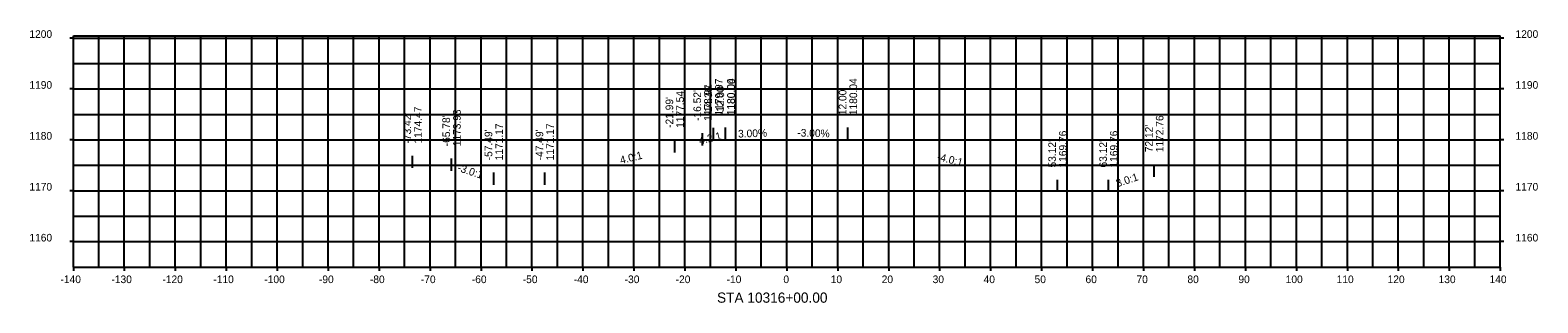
# Model space of a CAD drawing. Extents: x -148 to 147, y 1148 to 1202.
import ezdxf

# ---------------------------------------------------------------- set-up
doc = ezdxf.new("R2010")
doc.units = 0
for name, color, linetype in [('SheetBorder', 7, 'Continuous'), ('SheetGridMajor', 7, 'Continuous'), ('SheetGridMinor', 7, 'Continuous'), ('SheetText', 7, 'Continuous'), ('Text', 7, 'Continuous')]:
    doc.layers.add(name, color=color, linetype=linetype)

msp = doc.modelspace()

# ---------------------------------------------------------------- linework, layer by layer
at = {"layer": 'SheetBorder'}
for p, q in [((-140, 1200.4), (140, 1200.4)), ((-140, 1155), (-140, 1200.4)), ((140, 1155), (140, 1200.4)), ((-140, 1155), (140, 1155))]:
    msp.add_line(p, q, dxfattribs=at)
at = {"layer": 'SheetGridMajor'}
for p, q in [((-140, 1200), (-140.72, 1200)), ((-140, 1200), (140, 1200)), ((-130, 1155), (-130, 1200.4)), ((-120, 1155), (-120, 1200.4)), ((-110, 1155), (-110, 1200.4)), ((-100, 1155), (-100, 1200.4)), ((-90, 1155), (-90, 1200.4)), ((-80, 1155), (-80, 1200.4)), ((-70, 1155), (-70, 1200.4)), ((-60, 1155), (-60, 1200.4)), ((-50, 1155), (-50, 1200.4)), ((-40, 1155), (-40, 1200.4)), ((-30, 1155), (-30, 1200.4)), ((-20, 1155), (-20, 1200.4)), ((-10, 1155), (-10, 1200.4)), ((0, 1155), (0, 1200.4)), ((10, 1155), (10, 1200.4)), ((20, 1155), (20, 1200.4)), ((30, 1155), (30, 1200.4)), ((40, 1155), (40, 1200.4)), ((50, 1155), (50, 1200.4)), ((60, 1155), (60, 1200.4)), ((70, 1155), (70, 1200.4)), ((80, 1155), (80, 1200.4)), ((90, 1155), (90, 1200.4)), ((100, 1155), (100, 1200.4)), ((110, 1155), (110, 1200.4)), ((120, 1155), (120, 1200.4)), ((130, 1155), (130, 1200.4)), ((140.72, 1200), (140, 1200)), ((-140, 1190), (-140.72, 1190)), ((-140, 1190), (140, 1190)), ((140.72, 1190), (140, 1190)), ((-140, 1180), (-140.72, 1180)), ((-140, 1180), (140, 1180)), ((140.72, 1180), (140, 1180)), ((-140, 1170), (-140.72, 1170)), ((-140, 1170), (140, 1170)), ((140.72, 1170), (140, 1170)), ((-140, 1160), (-140.72, 1160)), ((-140, 1160), (140, 1160)), ((140.72, 1160), (140, 1160)), ((-140, 1155), (-140, 1154.28)), ((-130, 1155), (-130, 1154.28)), ((-120, 1155), (-120, 1154.28)), ((-110, 1155), (-110, 1154.28)), ((-100, 1155), (-100, 1154.28)), ((-90, 1155), (-90, 1154.28)), ((-80, 1155), (-80, 1154.28)), ((-70, 1155), (-70, 1154.28)), ((-60, 1155), (-60, 1154.28)), ((-50, 1155), (-50, 1154.28)), ((-40, 1155), (-40, 1154.28)), ((-30, 1155), (-30, 1154.28)), ((-20, 1155), (-20, 1154.28)), ((-10, 1155), (-10, 1154.28)), ((0, 1155), (0, 1154.28)), ((10, 1155), (10, 1154.28)), ((20, 1155), (20, 1154.28)), ((30, 1155), (30, 1154.28)), ((40, 1155), (40, 1154.28)), ((50, 1155), (50, 1154.28)), ((60, 1155), (60, 1154.28)), ((70, 1155), (70, 1154.28)), ((80, 1155), (80, 1154.28)), ((90, 1155), (90, 1154.28)), ((100, 1155), (100, 1154.28)), ((110, 1155), (110, 1154.28)), ((120, 1155), (120, 1154.28)), ((130, 1155), (130, 1154.28)), ((140, 1155), (140, 1154.28))]:
    msp.add_line(p, q, dxfattribs=at)
at = {"layer": 'SheetGridMinor'}
for p, q in [((-135, 1155), (-135, 1200.4)), ((-125, 1155), (-125, 1200.4)), ((-115, 1155), (-115, 1200.4)), ((-105, 1155), (-105, 1200.4)), ((-95, 1155), (-95, 1200.4)), ((-85, 1155), (-85, 1200.4)), ((-75, 1155), (-75, 1200.4)), ((-65, 1155), (-65, 1200.4)), ((-55, 1155), (-55, 1200.4)), ((-45, 1155), (-45, 1200.4)), ((-35, 1155), (-35, 1200.4)), ((-25, 1155), (-25, 1200.4)), ((-15, 1155), (-15, 1200.4)), ((-5, 1155), (-5, 1200.4)), ((5, 1155), (5, 1200.4)), ((15, 1155), (15, 1200.4)), ((25, 1155), (25, 1200.4)), ((35, 1155), (35, 1200.4)), ((45, 1155), (45, 1200.4)), ((55, 1155), (55, 1200.4)), ((65, 1155), (65, 1200.4)), ((75, 1155), (75, 1200.4)), ((85, 1155), (85, 1200.4)), ((95, 1155), (95, 1200.4)), ((105, 1155), (105, 1200.4)), ((115, 1155), (115, 1200.4)), ((125, 1155), (125, 1200.4)), ((135, 1155), (135, 1200.4)), ((-140, 1195), (140, 1195)), ((-140, 1185), (140, 1185)), ((-140, 1175), (140, 1175)), ((-140, 1165), (140, 1165))]:
    msp.add_line(p, q, dxfattribs=at)
at = {"layer": 'Text'}
for p, q in [((-16.52, 1178.91), (-16.52, 1181.31)), ((-14.36, 1179.97), (-14.36, 1182.37)), ((-12, 1180.04), (-12, 1182.44)), ((-12, 1180), (-12, 1182.4)), ((12, 1180.04), (12, 1182.44)), ((-21.99, 1177.54), (-21.99, 1179.94)), ((-73.42, 1174.47), (-73.42, 1176.87)), ((-65.78, 1173.93), (-65.78, 1176.33)), ((72.12, 1172.76), (72.12, 1175.16)), ((-57.49, 1171.17), (-57.49, 1173.57)), ((-47.49, 1171.17), (-47.49, 1173.57)), ((53.12, 1169.76), (53.12, 1172.16)), ((63.12, 1169.76), (63.12, 1172.16))]:
    msp.add_line(p, q, dxfattribs=at)

# ---------------------------------------------------------------- texts
at = {"layer": 'SheetText'}
for s, height, p in [('1200', 1.5, (-148.63, 1200.03)), ('1200', 1.5, (143, 1200.03)), ('1190', 1.5, (-148.63, 1190.03)), ('1190', 1.5, (143, 1190.03)), ('1180', 1.5, (-148.63, 1180.03)), ('1180', 1.5, (143, 1180.03)), ('1170', 1.5, (-148.63, 1170.03)), ('1170', 1.5, (143, 1170.03)), ('1160', 1.5, (-148.63, 1160.03)), ('1160', 1.5, (143, 1160.03)), ('-140', 1.5, (-142.53, 1151.85)), ('-130', 1.5, (-132.53, 1151.85)), ('-120', 1.5, (-122.53, 1151.85)), ('-110', 1.5, (-112.53, 1151.85)), ('-100', 1.5, (-102.53, 1151.85)), ('-90', 1.5, (-91.81, 1151.85)), ('-80', 1.5, (-81.81, 1151.85)), ('-70', 1.5, (-71.81, 1151.85)), ('-60', 1.5, (-61.81, 1151.85)), ('-50', 1.5, (-51.81, 1151.85)), ('-40', 1.5, (-41.81, 1151.85)), ('-30', 1.5, (-31.81, 1151.85)), ('-20', 1.5, (-21.81, 1151.85)), ('-10', 1.5, (-11.81, 1151.85)), ('0', 1.5, (-0.67, 1151.85)), ('10', 1.5, (8.62, 1151.85)), ('20', 1.5, (18.62, 1151.85)), ('30', 1.5, (28.62, 1151.85)), ('40', 1.5, (38.62, 1151.85)), ('50', 1.5, (48.62, 1151.85)), ('60', 1.5, (58.62, 1151.85)), ('70', 1.5, (68.62, 1151.85)), ('80', 1.5, (78.62, 1151.85)), ('90', 1.5, (88.62, 1151.85)), ('100', 1.5, (97.9, 1151.85)), ('110', 1.5, (107.9, 1151.85)), ('120', 1.5, (117.9, 1151.85)), ('130', 1.5, (127.9, 1151.85)), ('140', 1.5, (137.9, 1151.85)), ('STA 10316+00.00', 2.004, (-13.69, 1148))]:
    msp.add_text(s, height=height, dxfattribs=at).set_placement(p)
at = {"layer": 'Text'}
for s, rotation, p in [('1177.54', 90, (-20.19, 1182.34)), ("-16.52'", 90, (-16.82, 1183.71)), ('1178.91', 90, (-14.72, 1183.71)), ("-14.36'", 90, (-14.66, 1184.77)), ('1179.97', 90, (-12.56, 1184.77)), ("-12.00'", 90, (-12.3, 1184.8)), ("-12.00'", 90, (-12.3, 1184.84)), ('1180.00', 90, (-10.2, 1184.8)), ('1180.04', 90, (-10.2, 1184.84)), ("12.00'", 90, (11.7, 1184.84)), ('1180.04', 90, (13.8, 1184.84)), ('1174.47', 90, (-71.62, 1179.27)), ("-21.99'", 90, (-22.29, 1182.34)), ("-73.42'", 90, (-73.72, 1179.27)), ("-65.78'", 90, (-66.08, 1178.73)), ('1173.93', 90, (-63.98, 1178.73)), ('1172.76', 90, (73.92, 1177.56)), ("-57.49'", 90, (-57.79, 1175.97)), ('1171.17', 90, (-55.69, 1175.97)), ("-47.49'", 90, (-47.79, 1175.97)), ('1171.17', 90, (-45.69, 1175.97)), ('4.2:1', 13.5473, (-17.06, 1179.08)), ('3.00%', 1.7184, (-9.54, 1180.44)), ('-3.00%', 358.2816, (2.04, 1180.67)), ('1169.76', 90, (54.92, 1174.56)), ('1169.76', 90, (64.92, 1174.56)), ("72.12'", 90, (71.82, 1177.56)), ('4.0:1', 14.0362, (-32.54, 1175.24)), ("53.12'", 90, (52.82, 1174.56)), ("63.12'", 90, (62.82, 1174.56)), ('-3.0:1', 341.5668, (-64.76, 1173.92)), ('-4.0:1', 345.9638, (29.36, 1176.03)), ('3.0:1', 18.4332, (64.88, 1170.68))]:
    msp.add_text(s, height=1.5, rotation=rotation, dxfattribs=at).set_placement(p)

doc.saveas('drawing.dxf')
